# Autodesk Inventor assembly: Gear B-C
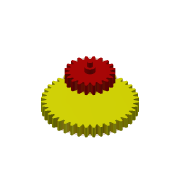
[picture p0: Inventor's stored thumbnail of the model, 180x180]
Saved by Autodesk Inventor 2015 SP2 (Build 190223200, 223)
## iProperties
Created: 2019-12
Part Number: Gear B-C
Document SubType Name: Assembly
Designer: Kuan_Lun Hsu
Author: Kuan_Lun Hsu
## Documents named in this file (3)
- C:\Users\Kuan_Lun Hsu\Desktop\Reverted Gear Train\Gear B-C.iam
- C:\Users\Kuan_Lun Hsu\Desktop\Reverted Gear Train\Gear A.ipt
- C:\Users\Kuan_Lun Hsu\Desktop\Reverted Gear Train\Gear D.ipt
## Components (2 placed, 2 different names)
1. Spur Gear1:1 — 貼合:1, 貼合:2, 貼合:3
2. Spur Gear2:1 — 貼合:1, 貼合:2, 貼合:3
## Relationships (3: Mate 3)
- 貼合:1 [Mate]: Spur Gear1:1 ↔ Spur Gear2:1
- 貼合:2 [Mate]: Spur Gear1:1 ↔ Spur Gear2:1
- 貼合:3 [Mate]: Spur Gear1:1 ↔ Spur Gear2:1
